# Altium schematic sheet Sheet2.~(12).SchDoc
size A3
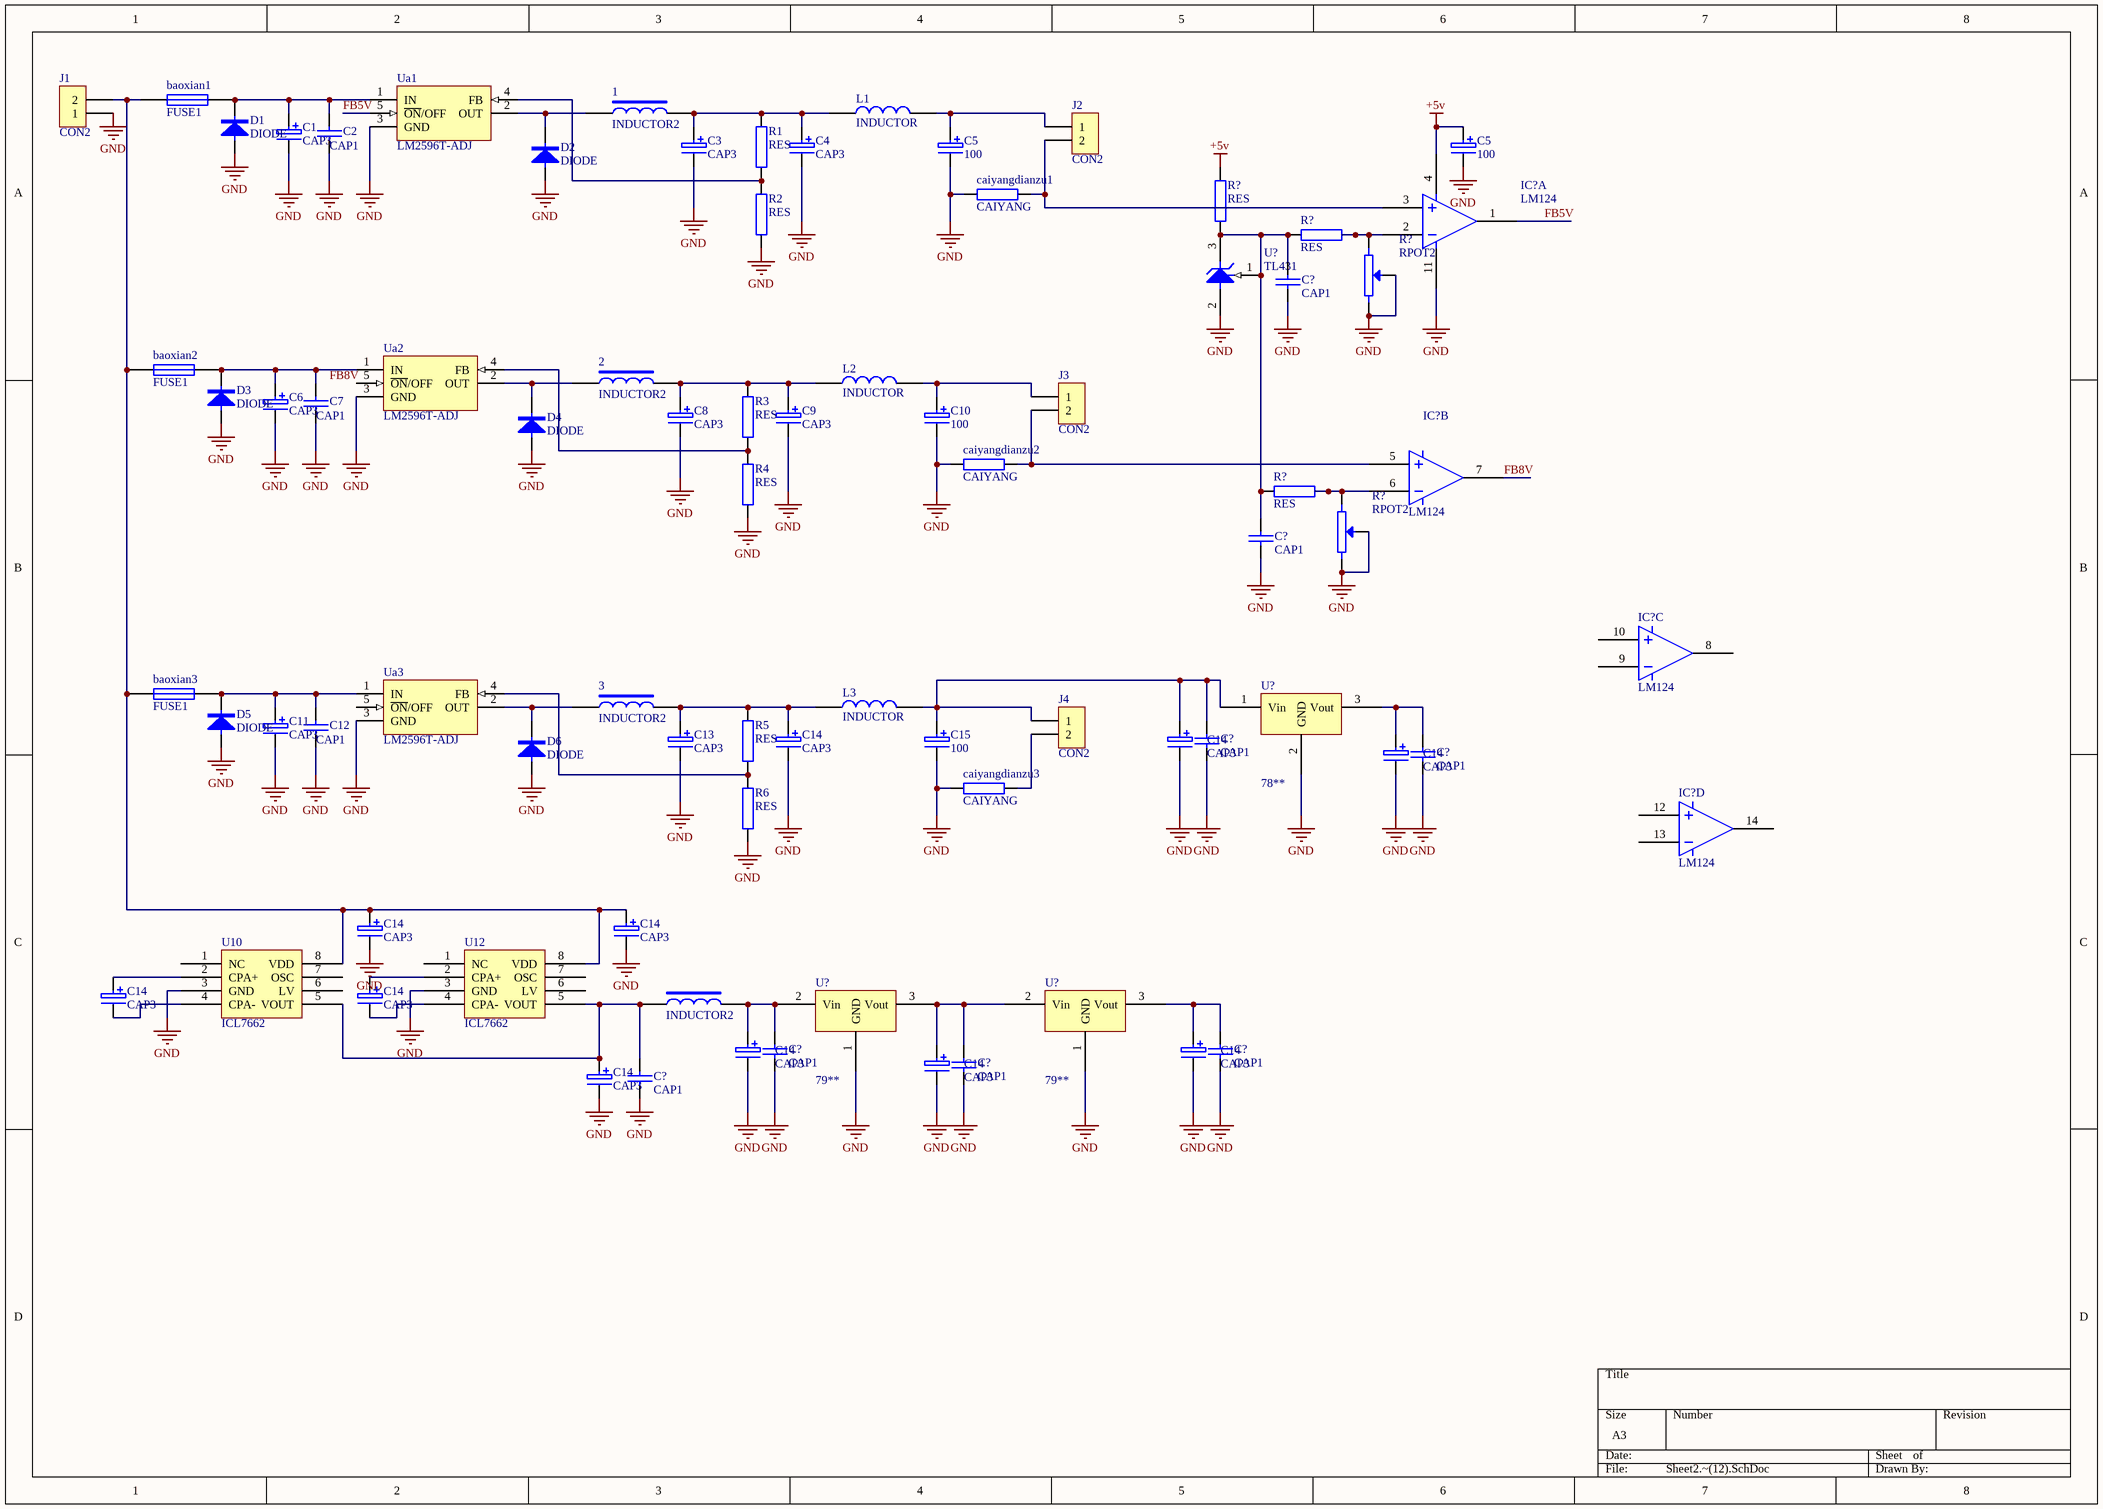
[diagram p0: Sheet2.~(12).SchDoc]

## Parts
(Parts that share a designator on the sheet are numbered #1, #2 ... from top to bottom, then left to right.)
1  INDUCTOR2
2  INDUCTOR2
3  INDUCTOR2
?  INDUCTOR2
baoxian1  FUSE1  [RAD0.5]
baoxian2  FUSE1  [RAD0.5]
baoxian3  FUSE1  [RAD0.5]
C1  CAP3  [RB2]
C2  CAP1  [RAD0.2]
C3  CAP3  [RB3]
C4  CAP3  [RB3]
C5#1  100  [RB1]
C5#2  100  [RB1]
C6  CAP3  [RB2]
C7  CAP1  [RAD0.2]
C8  CAP3  [RB3]
C9  CAP3  [RB3]
C10  100  [RB1]
C11  CAP3  [RB2]
C12  CAP1  [RAD0.2]
C13  CAP3  [RB3]
C14#1  CAP3  [RB3]
C14#2  CAP3  [RB3]
C14#3  CAP3  [RB3]
C14#4  CAP3  [RB3]
C14#5  CAP3  [RB3]
C14#6  CAP3  [RB3]
C14#7  CAP3  [RB3]
C14#8  CAP3  [RB3]
C14#9  CAP3  [RB3]
C14#10  CAP3  [RB3]
C14#11  CAP3  [RB3]
C15  100  [RB1]
C?#1  CAP1  [RAD0.15]
C?#2  CAP1  [RAD0.15]
C?#3  CAP1  [RAD0.15]
C?#4  CAP1  [RAD0.15]
C?#5  CAP1  [RAD0.15]
C?#6  CAP1  [RAD0.15]
C?#7  CAP1  [RAD0.15]
C?#8  CAP1  [RAD0.15]
caiyangdianzu1  CAIYANG  [AXIAL0.8]
caiyangdianzu2  CAIYANG  [AXIAL0.8]
caiyangdianzu3  CAIYANG  [AXIAL0.8]
D1  DIODE  [DIODE0.4]
D2  DIODE  [DIODE0.2]
D3  DIODE  [DIODE0.4]
D4  DIODE  [DIODE0.2]
D5  DIODE  [DIODE0.4]
D6  DIODE  [DIODE0.2]
IC?#1  LM124  [DIP-14]  (part A of 4)
IC?#2  LM124  [DIP-14]  (part B of 4)
IC?#3  LM124  [DIP-14]  (part C of 4)
IC?#4  LM124  [DIP-14]  (part D of 4)
J1  CON2  [BCON2]
J2  CON2  [BCON2]
J3  CON2  [BCON2]
J4  CON2  [BCON2]
L1  INDUCTOR  [LHF440]
L2  INDUCTOR  [LHF440]
L3  INDUCTOR  [LHF440]
R1  RES  [AXIAL0.3]
R2  RES  [AXIAL0.3]
R3  RES  [AXIAL0.3]
R4  RES  [AXIAL0.3]
R5  RES  [AXIAL0.3]
R6  RES  [AXIAL0.3]
R?#1  RES  [AXIAL0.3]
R?#2  RES  [AXIAL0.3]
R?#3  RPOT2  [VR5]
R?#4  RES  [AXIAL0.3]
R?#5  RPOT2  [VR5]
U10  ICL7662  [DIP-8]
U12  ICL7662  [DIP-8]
U?#1  TL431  [TO92B]
U?#2  78**  [TO257V]
U?#3  79**  [TO257V]
U?#4  79**  [TO257V]
Ua1  LM2596T-ADJ  [SIP-5]
Ua2  LM2596T-ADJ  [SIP-5]
Ua3  LM2596T-ADJ  [SIP-5]

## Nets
+5v: C5#2.1 IC?#1.4 R?#1.2
GND: C1.2 C2.2 C3.2 C4.2 C5#1.2 C5#2.2 C6.2 C7.2 C8.2 C9.2 C10.2 C11.2 C12.2 C13.2 C14#1.2 C14#2.2 C14#3.2 C14#4.2 C14#5.2 C14#8.2 C14#9.2 C14#10.2 C14#11.2 C15.2 C?#1.2 C?#2.2 C?#3.2 C?#4.2 C?#5.2 C?#6.2 C?#7.2 C?#8.2 caiyangdianzu1.2 caiyangdianzu2.2 caiyangdianzu3.2 D1.1 D2.1 D3.1 D4.1 D5.1 D6.1 IC?#1.11 J1.1 R2.1 R4.1 R6.1 R?#3.2(VT) R?#3.3 R?#5.2(VT) R?#5.3 U10.3(GND) U12.3(GND) U?#1.2(A) U?#2.2(GND) U?#3.1(GND) U?#4.1(GND) Ua1.3(GND) Ua2.3(GND) Ua3.3(GND)
FB5V: IC?#1.1 Ua1.5(~{ON}/OFF)
FB8V: IC?#2.7
Net1_1: 1.1 D2.2 Ua1.2(OUT)
Net1_2: 1.2 C3.1 C4.1 L1.1 R1.2
Net2_1: 2.1 D4.2 Ua2.2(OUT)
Net2_2: 2.2 C8.1 C9.1 L2.1 R3.2
Net3_1: 3.1 D6.2 Ua3.2(OUT)
Net3_2: 3.2 C13.1 C14#1.1 L3.1 R5.2
Net?_1: ?.1 C14#11.1 C?#8.1 U10.5(VOUT) U12.5(VOUT)
Net?_2: ?.2 C14#8.1 C?#5.1 U?#3.2(Vin)
Netbaoxian1_1: baoxian1.1 C1.1 C2.1 D1.2 Ua1.1(IN)
Netbaoxian1_2: baoxian1.2 baoxian2.2 baoxian3.2 C14#4.1 C14#5.1 J1.2 U10.8(VDD) U12.8(VDD)
Netbaoxian2_1: baoxian2.1 C6.1 C7.1 D3.2 Ua2.1(IN)
Netbaoxian3_1: baoxian3.1 C11.1 C12.1 D5.2 Ua3.1(IN)
NetC5#1_1: C5#1.1 J2.1 L1.2
NetC10_1: C10.1 J3.1 L2.2
NetC14#2_1: C14#2.1 C15.1 C?#3.1 J4.1 L3.2 U?#2.1(Vin)
NetC14#3_1: C14#3.1 C?#4.1 U?#2.3(Vout)
NetC14#6_1: C14#6.1 U10.2(CPA+)
NetC14#6_2: C14#6.2 U10.4(CPA-)
NetC14#7_1: C14#7.1 U12.2(CPA+)
NetC14#7_2: C14#7.2 U12.4(CPA-)
NetC14#9_1: C14#9.1 C?#6.1 U?#4.3(Vout)
NetC14#10_1: C14#10.1 C?#7.1 U?#3.3(Vout) U?#4.2(Vin)
NetC?#1_1: C?#1.1 C?#2.1 R?#1.1 R?#2.1 R?#4.1 U?#1.1(REF) U?#1.3(K)
Netcaiyangdianzu1_1: caiyangdianzu1.1 IC?#1.3 J2.2
Netcaiyangdianzu2_1: caiyangdianzu2.1 IC?#2.5 J3.2
Netcaiyangdianzu3_1: caiyangdianzu3.1 J4.2
NetIC?#1_2: IC?#1.2 R?#2.2 R?#3.1
NetIC?#2_6: IC?#2.6 R?#4.2 R?#5.1
NetR1_1: R1.1 R2.2 Ua1.4(FB)
NetR3_1: R3.1 R4.2 Ua2.4(FB)
NetR5_1: R5.1 R6.2 Ua3.4(FB)

Not connected (* = marked no-connect by the designer): IC?#3 8 9 10; IC?#4 12 13 14; U10 1(NC) 6(LV) 7(OSC); U12 1(NC) 6(LV) 7(OSC); Ua2 5(~{ON}/OFF); Ua3 5(~{ON}/OFF)

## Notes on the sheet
- Labels drawn without touching a wire or pin: FB8V

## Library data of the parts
baoxian1-baoxian3 = FUSE1: Fuse
C5#1 C5#2 C10 C15 = CAP3
caiyangdianzu1-caiyangdianzu3 = RES
J1-J4 = CON2: Connector
R?#3 R?#5 = RPOT2: Potentiometer
U?#1 = TL431: Programmable Voltage Reference
Ua1-Ua3 = LM2596T-5.0: Simple Switcher Power Converter 150 kHz 3A Step Down Voltage Regulator; PackageDocument: 2000; Note: Tab is connected to GND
